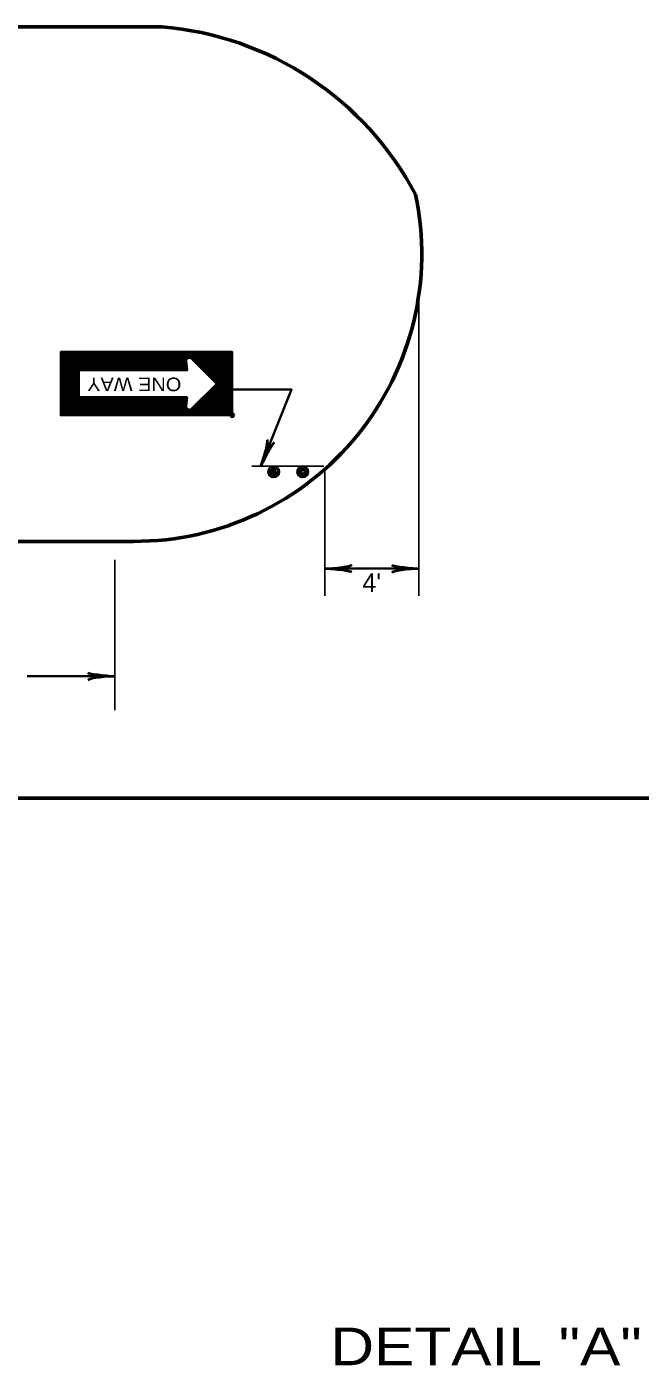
# Model space of a CAD drawing. Extents: x -133 to 547, y -328 to 112.
# Drawn here: x -11.7 to 53.5, y -178.8 to -36.5 of the extents above; entities that cross this region are included whole.
import ezdxf
from ezdxf.enums import TextEntityAlignment as Align

# ---------------------------------------------------------------- set-up
doc = ezdxf.new("R2010")
doc.units = 0
doc.header["$LTSCALE"] = 0.8
doc.header["$PDMODE"] = 32
doc.header["$PDSIZE"] = 0.4
doc.layers.add('1', color=7, linetype='Continuous', lineweight=35)
doc.layers.add('4', color=7, linetype='Continuous', lineweight=25)

msp = doc.modelspace()

# ---------------------------------------------------------------- linework, layer by layer
at = {"layer": '1', "lineweight": 53}
for p, q in [((-87.7097, -36.5198), (2.6132, -36.5198)), ((-0.3837, -91.2365), (-46.962, -91.2365)), ((-87.7097, -118.5198), (195.534, -118.5198))]:
    msp.add_line(p, q, dxfattribs=at)
at = {"layer": '1', "lineweight": 25}
for p, q in [((29.9637, -97.0253), (29.9637, -64.8886)), ((19.8473, -83.254), (12.1973, -83.254)), ((19.9463, -97.0253), (19.9463, -83.5655)), ((-2.3742, -109.1798), (-2.3742, -93.1798))]:
    msp.add_line(p, q, dxfattribs=at)
at = {"layer": '1'}
for p, q in [((-4.346, -71.0979), (-8.126, -74.8779)), ((-4.486, -71.0979), (-8.126, -74.7379)), ((-4.626, -71.0979), (-8.126, -74.5979)), ((-4.746, -71.0979), (-8.126, -74.4579)), ((-4.886, -71.0979), (-8.126, -74.3379)), ((-5.026, -71.0979), (-8.126, -74.1979)), ((-5.166, -71.0979), (-8.126, -74.0579)), ((-5.286, -71.0979), (-8.126, -73.9179)), ((-5.426, -71.0979), (-8.126, -73.7779)), ((-5.566, -71.0979), (-8.126, -73.6579)), ((-5.706, -71.0979), (-8.126, -73.5179)), ((-5.846, -71.0979), (-8.126, -73.3779)), ((-5.966, -71.0979), (-8.126, -73.2379)), ((-6.106, -71.0979), (-8.126, -73.0979)), ((-6.246, -71.0979), (-8.126, -72.9779)), ((-6.386, -71.0979), (-8.126, -72.8379)), ((-6.526, -71.0979), (-8.126, -72.6979)), ((-6.646, -71.0979), (-8.126, -72.5579)), ((-6.786, -71.0979), (-8.126, -72.4379)), ((-6.926, -71.0979), (-8.126, -72.2979)), ((-7.066, -71.0979), (-8.126, -72.1579)), ((-7.186, -71.0979), (-8.126, -72.0179)), ((-7.326, -71.0979), (-8.126, -71.8779)), ((-7.466, -71.0979), (-8.126, -71.7579)), ((-7.606, -71.0979), (-8.126, -71.6179)), ((-7.746, -71.0979), (-8.126, -71.4779)), ((-7.866, -71.0979), (-8.126, -71.3379)), ((-8.006, -71.0979), (-8.126, -71.1979)), ((-4.206, -71.0979), (-6.146, -73.0379)), ((-4.066, -71.0979), (-6.006, -73.0379)), ((-3.946, -71.0979), (-5.866, -73.0379)), ((-3.806, -71.0979), (-5.746, -73.0379)), ((-3.666, -71.0979), (-5.606, -73.0379)), ((-3.526, -71.0979), (-5.466, -73.0379)), ((-3.386, -71.0979), (-5.326, -73.0379)), ((-3.266, -71.0979), (-5.206, -73.0379)), ((-3.126, -71.0979), (-5.066, -73.0379)), ((-2.986, -71.0979), (-4.926, -73.0379)), ((-2.846, -71.0979), (-4.786, -73.0379)), ((-2.706, -71.0979), (-4.646, -73.0379)), ((-2.586, -71.0979), (-4.526, -73.0379)), ((-2.446, -71.0979), (-4.386, -73.0379)), ((-2.306, -71.0979), (-4.246, -73.0379)), ((-2.166, -71.0979), (-4.106, -73.0379)), ((-2.046, -71.0979), (-3.966, -73.0379)), ((-1.906, -71.0979), (-3.846, -73.0379)), ((-1.766, -71.0979), (-3.706, -73.0379)), ((-1.626, -71.0979), (-3.566, -73.0379)), ((-1.486, -71.0979), (-3.426, -73.0379)), ((-1.366, -71.0979), (-3.286, -73.0379)), ((-1.226, -71.0979), (-3.166, -73.0379)), ((-1.086, -71.0979), (-3.026, -73.0379)), ((-0.946, -71.0979), (-2.886, -73.0379)), ((-0.806, -71.0979), (-2.746, -73.0379)), ((-0.686, -71.0979), (-2.626, -73.0379)), ((-0.546, -71.0979), (-2.486, -73.0379)), ((-0.406, -71.0979), (-2.346, -73.0379)), ((-0.266, -71.0979), (-2.206, -73.0379)), ((-0.146, -71.0979), (-2.066, -73.0379)), ((-0.006, -71.0979), (-1.946, -73.0379)), ((0.134, -71.0979), (-1.806, -73.0379)), ((0.274, -71.0979), (-1.666, -73.0379)), ((0.414, -71.0979), (-1.526, -73.0379)), ((0.534, -71.0979), (-1.386, -73.0379)), ((0.674, -71.0979), (-1.266, -73.0379)), ((0.814, -71.0979), (-1.126, -73.0379)), ((0.954, -71.0979), (-0.986, -73.0379)), ((1.094, -71.0979), (-0.846, -73.0379)), ((1.214, -71.0979), (-0.726, -73.0379)), ((1.354, -71.0979), (-0.586, -73.0379)), ((1.494, -71.0979), (-0.446, -73.0379)), ((1.634, -71.0979), (-0.306, -73.0379)), ((1.774, -71.0979), (-0.166, -73.0379)), ((1.894, -71.0979), (-0.046, -73.0379)), ((2.034, -71.0979), (0.094, -73.0379)), ((2.174, -71.0979), (0.234, -73.0379)), ((2.314, -71.0979), (0.374, -73.0379)), ((2.434, -71.0979), (0.514, -73.0379)), ((2.574, -71.0979), (0.634, -73.0379)), ((2.714, -71.0979), (0.774, -73.0379)), ((2.854, -71.0979), (0.914, -73.0379)), ((2.994, -71.0979), (1.054, -73.0379)), ((3.114, -71.0979), (1.194, -73.0379)), ((3.254, -71.0979), (1.314, -73.0379)), ((3.394, -71.0979), (1.454, -73.0379)), ((3.534, -71.0979), (1.594, -73.0379)), ((3.674, -71.0979), (1.734, -73.0379)), ((3.794, -71.0979), (1.854, -73.0379)), ((3.934, -71.0979), (1.994, -73.0379)), ((4.074, -71.0979), (2.134, -73.0379)), ((4.214, -71.0979), (2.274, -73.0379)), ((4.354, -71.0979), (2.414, -73.0379)), ((4.474, -71.0979), (2.534, -73.0379)), ((4.614, -71.0979), (2.674, -73.0379)), ((4.754, -71.0979), (2.814, -73.0379)), ((4.894, -71.0979), (2.954, -73.0379)), ((5.014, -71.0979), (3.094, -73.0379)), ((5.154, -71.0979), (3.214, -73.0379)), ((5.294, -71.0979), (3.354, -73.0379)), ((5.434, -71.0979), (3.494, -73.0379)), ((5.574, -71.0979), (3.634, -73.0379)), ((5.694, -71.0979), (3.774, -73.0379)), ((5.834, -71.0979), (3.894, -73.0379)), ((5.974, -71.0979), (4.034, -73.0379)), ((6.114, -71.0979), (5.494, -71.7179)), ((6.254, -71.0979), (5.634, -71.7179)), ((6.374, -71.0979), (5.734, -71.7379)), ((6.514, -71.0979), (5.794, -71.7979)), ((6.654, -71.0979), (5.874, -71.8779)), ((6.794, -71.0979), (5.934, -71.9379)), ((6.914, -71.0979), (6.014, -72.0179)), ((7.054, -71.0979), (6.074, -72.0779)), ((7.194, -71.0979), (6.134, -72.1379)), ((7.334, -71.0979), (6.214, -72.2179)), ((7.474, -71.0979), (6.274, -72.2779)), ((7.594, -71.0979), (6.354, -72.3579)), ((7.734, -71.0979), (6.414, -72.4179)), ((7.874, -71.0979), (6.474, -72.4779)), ((8.014, -71.0979), (6.554, -72.5579)), ((8.154, -71.0979), (6.614, -72.6179)), ((8.274, -71.0979), (6.694, -72.6979)), ((8.414, -71.0979), (6.754, -72.7579)), ((8.554, -71.0979), (6.814, -72.8179)), ((8.694, -71.0979), (6.894, -72.8979)), ((8.834, -71.0979), (6.954, -72.9579)), ((8.954, -71.0979), (7.034, -73.0379)), ((9.094, -71.0979), (7.094, -73.0979)), ((9.234, -71.0979), (7.154, -73.1579)), ((9.374, -71.0979), (7.234, -73.2379)), ((9.494, -71.0979), (7.294, -73.2979)), ((9.634, -71.0979), (7.374, -73.3579)), ((9.774, -71.0979), (7.434, -73.4379)), ((9.914, -71.0979), (7.494, -73.4979)), ((10.054, -71.0979), (7.574, -73.5779)), ((5.234, -71.9779), (4.174, -73.0379)), ((5.234, -72.1179), (4.314, -73.0379)), ((5.234, -72.2379), (4.434, -73.0379)), ((5.254, -72.3579), (4.574, -73.0379)), ((5.254, -72.4779), (4.714, -73.0379)), ((5.754, -71.7579), (8.474, -74.4779)), ((10.114, -71.1579), (7.634, -73.6379)), ((10.114, -71.2979), (7.714, -73.6979)), ((10.114, -71.4379), (7.774, -73.7779)), ((10.114, -71.5579), (7.834, -73.8379)), ((10.114, -71.6979), (7.914, -73.9179)), ((10.114, -71.8379), (7.974, -73.9779)), ((10.114, -71.9779), (8.034, -74.0379)), ((10.114, -72.1179), (8.114, -74.1179)), ((10.114, -72.2379), (8.174, -74.1779)), ((10.114, -72.3779), (8.254, -74.2579)), ((10.114, -72.5179), (8.314, -74.3179)), ((-6.206, -73.0979), (-8.126, -75.0179)), ((-6.206, -73.2379), (-8.126, -75.1379)), ((-6.206, -73.3779), (-8.126, -75.2779)), ((-6.206, -73.4979), (-8.126, -75.4179)), ((-6.206, -73.6379), (-8.126, -75.5579)), ((-6.206, -73.7779), (-8.126, -75.6779)), ((-6.206, -73.9179), (-8.126, -75.8179)), ((5.274, -72.6179), (4.854, -73.0379)), ((5.274, -72.7379), (4.994, -73.0379)), ((5.294, -72.8579), (5.114, -73.0379)), ((10.114, -72.9179), (5.234, -77.8179)), ((5.294, -72.9779), (5.254, -73.0379)), ((10.114, -73.0579), (5.354, -77.8179)), ((10.114, -73.1979), (5.494, -77.8179)), ((10.114, -73.3379), (5.634, -77.8179)), ((10.114, -73.4579), (5.774, -77.8179)), ((10.114, -73.5979), (5.914, -77.8179)), ((10.114, -73.7379), (6.034, -77.8179)), ((10.114, -73.8779), (6.174, -77.8179)), ((10.114, -72.6579), (8.374, -74.3779)), ((10.114, -72.7979), (8.454, -74.4579)), ((-6.206, -74.0379), (-8.126, -75.9579)), ((-6.206, -74.1779), (-8.126, -76.0979)), ((-6.206, -74.3179), (-8.126, -76.2379)), ((-6.206, -74.4579), (-8.126, -76.3579)), ((-6.206, -74.5979), (-8.126, -76.4979)), ((-6.206, -74.7179), (-8.126, -76.6379)), ((-6.206, -74.8579), (-8.126, -76.7779)), ((-6.206, -74.9979), (-8.126, -76.9179)), ((-6.206, -75.1379), (-8.126, -77.0379)), ((-6.206, -75.2779), (-8.126, -77.1779)), ((-6.206, -75.3979), (-8.126, -77.3179)), ((8.474, -74.4779), (5.754, -77.1779)), ((10.114, -74.0179), (6.314, -77.8179)), ((10.114, -74.1379), (6.454, -77.8179)), ((10.114, -74.2779), (6.594, -77.8179)), ((10.114, -74.4179), (6.714, -77.8179)), ((10.114, -74.5579), (6.854, -77.8179)), ((10.114, -74.6979), (6.994, -77.8179)), ((10.114, -74.8179), (7.134, -77.8179)), ((10.114, -74.9579), (7.254, -77.8179)), ((10.114, -75.0979), (7.394, -77.8179)), ((10.114, -75.2379), (7.534, -77.8179)), ((10.114, -75.3779), (7.674, -77.8179)), ((-6.206, -75.5379), (-8.126, -77.4579)), ((-6.206, -75.6779), (-8.126, -77.5979)), ((-6.206, -75.8179), (-8.126, -77.7179)), ((-6.166, -75.9179), (-8.086, -77.8179)), ((-6.046, -75.9179), (-7.946, -77.8179)), ((-5.906, -75.9179), (-7.806, -77.8179)), ((-5.766, -75.9179), (-7.666, -77.8179)), ((-5.626, -75.9179), (-7.526, -77.8179)), ((-5.506, -75.9179), (-7.406, -77.8179)), ((-5.366, -75.9179), (-7.266, -77.8179)), ((-5.226, -75.9179), (-7.126, -77.8179)), ((-5.086, -75.9179), (-6.986, -77.8179)), ((-4.946, -75.9179), (-6.866, -77.8179)), ((-4.826, -75.9179), (-6.726, -77.8179)), ((-4.686, -75.9179), (-6.586, -77.8179)), ((-4.546, -75.9179), (-6.446, -77.8179)), ((-4.406, -75.9179), (-6.306, -77.8179)), ((-4.266, -75.9179), (-6.186, -77.8179)), ((-4.146, -75.9179), (-6.046, -77.8179)), ((-4.006, -75.9179), (-5.906, -77.8179)), ((-3.866, -75.9179), (-5.766, -77.8179)), ((-3.726, -75.9179), (-5.626, -77.8179)), ((-3.606, -75.9179), (-5.506, -77.8179)), ((-3.466, -75.9179), (-5.366, -77.8179)), ((-3.326, -75.9179), (-5.226, -77.8179)), ((-3.186, -75.9179), (-5.086, -77.8179)), ((-3.046, -75.9179), (-4.946, -77.8179)), ((-2.926, -75.9179), (-4.826, -77.8179)), ((-2.786, -75.9179), (-4.686, -77.8179)), ((-2.646, -75.9179), (-4.546, -77.8179)), ((-2.506, -75.9179), (-4.406, -77.8179)), ((-2.366, -75.9179), (-4.286, -77.8179)), ((-2.246, -75.9179), (-4.146, -77.8179)), ((-2.106, -75.9179), (-4.006, -77.8179)), ((-1.966, -75.9179), (-3.866, -77.8179)), ((-1.826, -75.9179), (-3.726, -77.8179)), ((-1.686, -75.9179), (-3.606, -77.8179)), ((-1.566, -75.9179), (-3.466, -77.8179)), ((-1.426, -75.9179), (-3.326, -77.8179)), ((-1.286, -75.9179), (-3.186, -77.8179)), ((-1.146, -75.9179), (-3.046, -77.8179)), ((-1.026, -75.9179), (-2.926, -77.8179)), ((-0.886, -75.9179), (-2.786, -77.8179)), ((-0.746, -75.9179), (-2.646, -77.8179)), ((-0.606, -75.9179), (-2.506, -77.8179)), ((-0.466, -75.9179), (-2.366, -77.8179)), ((-0.346, -75.9179), (-2.246, -77.8179)), ((-0.206, -75.9179), (-2.106, -77.8179)), ((-0.066, -75.9179), (-1.966, -77.8179)), ((0.074, -75.9179), (-1.826, -77.8179)), ((0.214, -75.9179), (-1.706, -77.8179)), ((0.334, -75.9179), (-1.566, -77.8179)), ((0.474, -75.9179), (-1.426, -77.8179)), ((0.614, -75.9179), (-1.286, -77.8179)), ((0.754, -75.9179), (-1.146, -77.8179)), ((0.894, -75.9179), (-1.026, -77.8179)), ((1.014, -75.9179), (-0.886, -77.8179)), ((1.154, -75.9179), (-0.746, -77.8179)), ((1.294, -75.9179), (-0.606, -77.8179)), ((1.434, -75.9179), (-0.466, -77.8179)), ((1.554, -75.9179), (-0.346, -77.8179)), ((1.694, -75.9179), (-0.206, -77.8179)), ((1.834, -75.9179), (-0.066, -77.8179)), ((1.974, -75.9179), (0.074, -77.8179)), ((2.114, -75.9179), (0.194, -77.8179)), ((2.234, -75.9179), (0.334, -77.8179)), ((2.374, -75.9179), (0.474, -77.8179)), ((2.514, -75.9179), (0.614, -77.8179)), ((2.654, -75.9179), (0.754, -77.8179)), ((2.794, -75.9179), (0.874, -77.8179)), ((2.914, -75.9179), (1.014, -77.8179)), ((3.054, -75.9179), (1.154, -77.8179)), ((3.194, -75.9179), (1.294, -77.8179)), ((3.334, -75.9179), (1.434, -77.8179)), ((3.454, -75.9179), (1.554, -77.8179)), ((3.594, -75.9179), (1.694, -77.8179)), ((3.734, -75.9179), (1.834, -77.8179)), ((3.874, -75.9179), (1.974, -77.8179)), ((4.014, -75.9179), (2.114, -77.8179)), ((4.134, -75.9179), (2.234, -77.8179)), ((4.274, -75.9179), (2.374, -77.8179)), ((4.414, -75.9179), (2.514, -77.8179)), ((4.554, -75.9179), (2.654, -77.8179)), ((4.694, -75.9179), (2.774, -77.8179)), ((4.814, -75.9179), (2.914, -77.8179)), ((4.954, -75.9179), (3.054, -77.8179)), ((5.094, -75.9179), (3.194, -77.8179)), ((5.234, -75.9179), (3.334, -77.8179)), ((5.294, -75.9779), (3.454, -77.8179)), ((5.294, -76.1179), (3.594, -77.8179)), ((5.274, -76.2779), (3.734, -77.8179)), ((5.254, -76.4179), (3.874, -77.8179)), ((5.254, -76.5779), (4.014, -77.8179)), ((5.234, -76.7179), (4.134, -77.8179)), ((10.114, -75.4979), (7.814, -77.8179)), ((10.114, -75.6379), (7.934, -77.8179)), ((10.114, -75.7779), (8.074, -77.8179)), ((10.114, -75.9179), (8.214, -77.8179)), ((10.114, -76.0379), (8.354, -77.8179)), ((10.114, -76.1779), (8.494, -77.8179)), ((10.114, -76.3179), (8.614, -77.8179)), ((10.114, -76.4579), (8.754, -77.8179)), ((10.114, -76.5979), (8.894, -77.8179)), ((10.114, -76.7179), (9.034, -77.8179)), ((5.214, -76.8579), (4.274, -77.8179)), ((5.234, -76.9979), (4.414, -77.8179)), ((5.274, -77.0779), (4.554, -77.8179)), ((5.354, -77.1579), (4.674, -77.8179)), ((5.434, -77.1979), (4.814, -77.8179)), ((5.534, -77.2379), (4.954, -77.8179)), ((5.694, -77.2179), (5.094, -77.8179)), ((10.114, -76.8579), (9.174, -77.8179)), ((10.114, -76.9979), (9.294, -77.8179)), ((10.114, -77.1379), (9.434, -77.8179)), ((10.114, -77.2779), (9.574, -77.8179)), ((10.114, -77.3979), (9.714, -77.8179)), ((10.114, -77.5379), (9.834, -77.8179)), ((10.114, -77.6779), (9.974, -77.8179)), ((19.9463, -94.1312), (29.9637, -94.1312)), ((-11.6997, -105.5739), (-2.3742, -105.5739))]:
    msp.add_line(p, q, dxfattribs=at)
msp.add_lwpolyline([(10.114, -77.8179), (-8.126, -77.8179), (-8.126, -71.0979), (10.114, -71.0979)], close=True, dxfattribs=at)
for points in [[(5.214, -76.8579), (5.314, -75.9179), (-6.206, -75.9179), (-6.206, -73.0379), (5.314, -73.0379), (5.214, -72.0779)], [(13.1405, -83.254), (16.42, -75.0936), (10.114, -75.0936)]]:
    msp.add_lwpolyline(points, dxfattribs=at)
at = {"layer": '1', "lineweight": 53}
for centre, radius, start, end in [((-0.1704, -70.0592), 33.6546, 27.83224, 85.25551), ((-0.3008, -60.6809), 30.5557, 269.84467, 11.96498)]:
    msp.add_arc(centre, radius, start, end, dxfattribs=at)
at = {"layer": '1'}
for centre, start, end in [((5.5717, -72.054), 58.76645, 183.36449), ((5.5717, -76.8876), 176.63551, 301.23355)]:
    msp.add_arc(centre, 0.3492, start, end, dxfattribs=at)
at = {"layer": '1', "lineweight": 40}
for centre, major_axis, ratio, start_param, end_param in [((13.291, -82.1385), (-0.521, -1.7151), 0.122415, 0.89635335, 3.14159265), ((13.7547, -82.2932), (-0.8179, -1.5643), 0.07063, 3.14071475, 5.41810995), ((21.0375, -93.8549), (-1.7857, -0.1562), 0.122415, 0.89635335, 3.14159265), ((21.0375, -93.8549), (-1.7857, -0.1562), 0.122415, 0.89635335, 3.14159265), ((28.8432, -93.9196), (1.7565, -0.1757), 0.07063, 3.14071475, 5.41810995), ((21.0668, -94.3428), (-1.7565, 0.1757), 0.07063, 3.14071475, 5.41810995), ((21.0668, -94.3428), (-1.7565, 0.1757), 0.07063, 3.14071475, 5.41810995), ((28.8726, -94.4075), (1.7857, 0.1562), 0.122415, 0.89635335, 3.14159265), ((-3.4947, -105.3623), (1.7565, -0.1757), 0.07063, 3.14071475, 5.41810995), ((-3.4654, -105.8502), (1.7857, 0.1562), 0.122415, 0.89635335, 3.14159265)]:
    msp.add_ellipse(centre, major_axis=major_axis, ratio=ratio, start_param=start_param, end_param=end_param, dxfattribs=at)
at = {"layer": '1', "lineweight": 25}
for points in [[(14.5673, -83.374), (14.8673, -83.584), (15.0173, -83.884), (14.9273, -84.094), (14.5973, -84.304), (14.2673, -84.304), (13.9373, -83.974), (14.1473, -83.584), (14.5673, -83.374), (14.7473, -83.494), (14.8973, -83.584), (14.9573, -83.854), (14.7473, -84.214), (14.6273, -84.364), (14.2073, -84.124), (14.2673, -83.824), (14.3273, -83.644), (14.4473, -83.584), (14.6273, -83.584), (14.7173, -83.764), (14.7473, -84.094), (14.5373, -84.094), (14.3873, -84.124), (14.2673, -83.944), (14.4773, -83.674), (14.6573, -83.794), (14.6873, -83.914), (14.4773, -83.944), (14.5073, -84.004), (14.0573, -83.674), (14.4473, -84.394), (14.5373, -83.974), (14.8073, -84.244), (15.1073, -83.824), (14.4773, -83.944), (14.5973, -83.554), (14.1773, -83.644), (14.4773, -83.944)], [(17.5973, -83.314), (17.9273, -83.464), (18.1373, -83.794), (18.0773, -84.154), (17.6873, -84.394), (17.3273, -84.184), (17.1173, -83.884), (17.1773, -83.674), (17.5973, -83.314), (17.8073, -83.554), (17.9873, -83.644), (18.0173, -83.824), (17.8073, -84.244), (17.5973, -84.214), (17.4473, -84.094), (17.2073, -83.944), (17.3873, -83.584), (17.6273, -83.524), (17.7773, -83.644), (17.8673, -83.824), (17.8073, -84.004), (17.7473, -84.124), (17.4473, -84.034), (17.5073, -83.824), (17.5073, -83.704), (17.7473, -83.704), (17.8073, -83.884), (17.4773, -84.004), (17.4173, -83.974), (17.1473, -83.704), (17.5373, -84.274), (17.4473, -84.004), (17.8973, -84.304), (18.1073, -83.794), (17.4773, -84.004), (17.4473, -83.464), (17.3573, -83.584), (17.4773, -84.004)]]:
    msp.add_spline(points, degree=3, dxfattribs=at)
at = {"layer": '1'}
msp.add_point((10.114, -77.8179), dxfattribs=at)
at = {"layer": '4'}
for centre in [(14.5192, -83.8444), (17.6044, -83.8442)]:
    msp.add_circle(centre, 0.615, dxfattribs=at)

# ---------------------------------------------------------------- texts
at = {"layer": '1', "width": 1.1}
msp.add_text('ONE WAY', height=1.44, rotation=180, dxfattribs=at).set_placement((-0.3063, -73.8179), align=Align.CENTER)
at = {"layer": '1'}
msp.add_text("4'", height=2, dxfattribs=at).set_placement((23.9404, -96.6251))
at = {"layer": '1', "width": 1.2}
msp.add_text('DETAIL "A"', height=4, dxfattribs=at).set_placement((37.1024, -178.8264), align=Align.CENTER)

doc.saveas('drawing.dxf')
